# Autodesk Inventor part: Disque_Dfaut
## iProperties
Created: 2006-03
Part Number: Disque_Dfaut
Document SubType Name: Modeling
Designer: Flavien MARTY
Author: Flavien MARTY
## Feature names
1. Base1
